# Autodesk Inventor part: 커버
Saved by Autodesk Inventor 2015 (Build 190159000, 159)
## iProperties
Created: 2025-11
Part Number: 커버
Material: 일반
Document SubType Name: Modeling
Designer: user
Density: 1 g/cm^3
Appearance: 기본값
Author: user
Author: jhkim
Creation Date: 2025-10-31
Sending System: Autodesk Inventor 2026
Preprocessor: ST-DEVELOPER v20.1
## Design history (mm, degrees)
node "커버1"
node "솔리드2"
node "기준1"
